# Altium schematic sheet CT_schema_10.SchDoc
size 274 x 160 mm
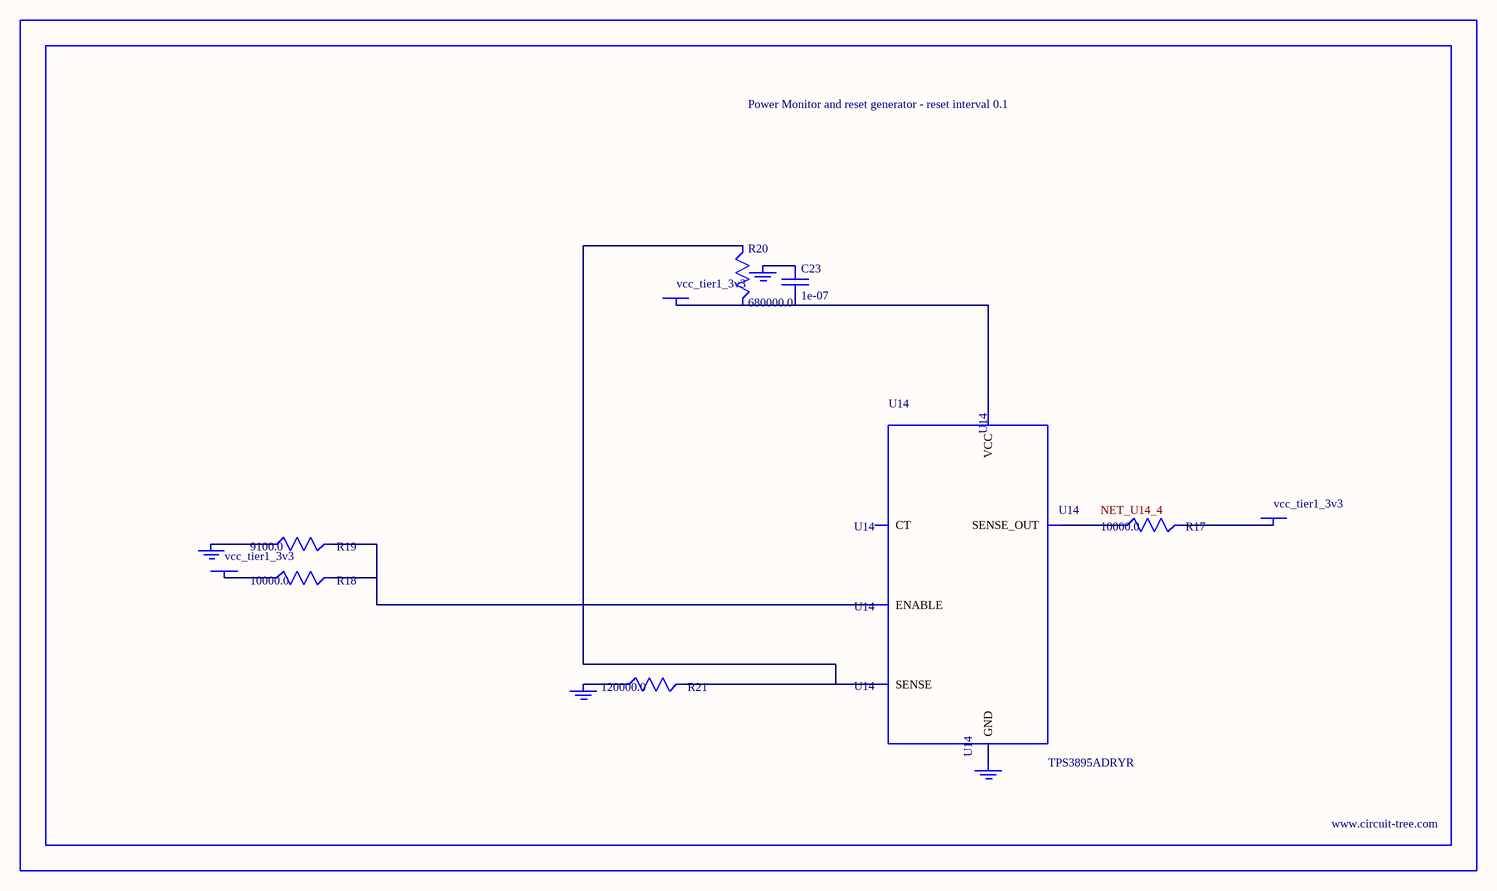
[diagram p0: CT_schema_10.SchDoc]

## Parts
BORDER9  (no value)
C23  1e-07  [C0402]
GND_INSTANCE_9_0  (no value)
GND_INSTANCE_9_1  (no value)
GND_INSTANCE_9_2  (no value)
GND_INSTANCE_9_3  (no value)
POWER_INSTANCE_9_0  vcc_tier1_3v3
POWER_INSTANCE_9_1  vcc_tier1_3v3
POWER_INSTANCE_9_2  vcc_tier1_3v3
R17  10000.0  [R0603]
R18  10000.0  [R0603]
R19  9100.0  [R0603]
R20  680000.0  [R0603]
R21  120000.0  [R0603]
U14  TPS3895ADRYR  [SON-6]

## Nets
NetC23_1: C23.1 GND_INSTANCE_9_2.0(GND)
NetC23_2: C23.2 POWER_INSTANCE_9_2.0(PWR) R20.2 U14.6(VCC)
NetGND_INSTANCE_9_0_0: GND_INSTANCE_9_0.0(GND) R19.1
NetGND_INSTANCE_9_1_0: GND_INSTANCE_9_1.0(GND) R21.1
NetGND_INSTANCE_9_3_0: GND_INSTANCE_9_3.0(GND) U14.2(GND)
NetPOWER_INSTANCE_9_0_0: POWER_INSTANCE_9_0.0(PWR) R18.1
NetPOWER_INSTANCE_9_1_0: POWER_INSTANCE_9_1.0(PWR) R17.2
NetR17_1: R17.1 U14.4(SENSE_OUT)
NetR18_2: R18.2 R19.2 U14.1(ENABLE)
NetR20_1: R20.1 R21.2 U14.3(SENSE)

Not connected (* = marked no-connect by the designer): U14 5(CT)

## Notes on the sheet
- Labels drawn without touching a wire or pin: NET_U14_4

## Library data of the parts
BORDER9 = BORDER_PAGE9
C23 = C0402C104K3RACTU
GND_INSTANCE_9_0-GND_INSTANCE_9_3 = GND
POWER_INSTANCE_9_0-POWER_INSTANCE_9_2 = PWR
R17 R18 = RC0603JR-0710KL
R19 = RC0603JR-079K1L
R20 = RC0603JR-07680KL
R21 = RC0603JR-07120KL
